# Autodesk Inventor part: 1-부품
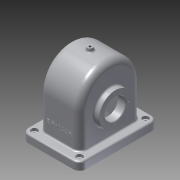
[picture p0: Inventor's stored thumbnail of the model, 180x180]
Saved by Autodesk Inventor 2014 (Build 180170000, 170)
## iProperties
Created: 2016-10
Part Number: 1-부품
Material: 알루미늄-6061
Document SubType Name: Modeling
Designer: SEC
Density: 2.71 g/cm^3
Mass: 1147.19 g
Surface Area: 1199.22 cm^2
Volume: 423.317 cm^3
Appearance: 알루미늄 - 평지
Author: SEC
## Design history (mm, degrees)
sketch "스케치2"
  geometry: L1 (-43, -75)-(43, -75); L2 (55, -63)-(55, 63); L3 (43, 75)-(-43, 75); L4 (-55, 63)-(-55, -63); A1 r 12 centre (-43, 63) between (-43, 75) and (-55, 63); A2 r 12 centre (43, 63) between (55, 63) and (43, 75); A3 r 12 centre (43, -63) between (43, -75) and (55, -63); A4 r 12 centre (-43, -63) between (-55, -63) and (-43, -75); 6 further points
  constraints: 8 end point, 8 point on circle, 8 tangent, 6 point on line, 4 centre point, 3 equal radius, 2 midpoint, 2 parallel, 1 horizontal, 1 horizontal alignment, 1 perpendicular, 1 vertical alignment
  dimensions: "d0" = 110 distance of point (55, 75) point (-55, 75); "d1" = 150 distance of point (55, -75) point (55, 75); "d2" = 12 radius of A1
extrude "돌출1" new body sketch "스케치2" distance "d3" = 15; taper "d4" = 0 deg
sketch "스케치3"
  geometry: A1 r 12 centre (-43, 63) between (-43, 75) and (-55, 63) reference; A2 r 12 centre (-43, -63) between (-55, -63) and (-43, -75) reference; A3 r 12 centre (43, -63) between (43, -75) and (55, -63) reference; A4 r 12 centre (43, 63) between (55, 63) and (43, 75) reference; 5 further points
  constraints: 4 coincident
hole "구멍1" sketch "스케치3" at (-43, -63), (43, -63), (-43, 63), (43, 63) diameter "d7" = 5; stored, may be unused: countersink angle "d11" = 90 deg, drill point angle "d13" = 118 deg; dims "d8" = 6, "d9" = 12, "d10" = 5, "d12" = 8
sketch "스케치5"
  geometry: L1 (58, 80)-(58, 0); L2 (-58, 80)-(-58, 0); L3 (63, 0)-(-63, 0) reference; L4 (-58, 0)-(58, 0); A1 r 58 centre (0, 80) between (58, 80) and (-58, 80); 2 further points
  constraints: 6 end point, 2 point on circle, 2 tangent, 1 centre point, 1 collinear, 1 midpoint, 1 parallel, 1 point on line, 1 vertical, 1 vertical alignment
  dimensions: "d14" = 116 diameter of A1; "d15" = 80 distance from line of L3 A1.centre
extrude "돌출2" join sketch "스케치5" stored distance "d16" = 77; taper "d17" = 0 deg
sketch "스케치6"
  geometry: L1 (-58, 15)-(58, 15) reference; L2 (-58, 80)-(-58, 15) reference; L3 (58, 15)-(58, 80) reference; L4 (-52, 80)-(-52, 0); L5 (52, 0)-(52, 80); L6 (52, 0)-(-52, 0); L7 (63, 0)-(-63, 0) reference; A1 r 58 centre (0, 80) between (58, 80) and (-58, 80) reference; A2 r 52 centre (0, 80) between (52, 80) and (-52, 80); 2 further points
  constraints: 6 end point, 2 midpoint, 2 point on circle, 1 centre point, 1 parallel, 1 perpendicular, 1 tangent, 1 other
  dimensions: "d18" = 6 radial gap between concentric circles of A2 A1
extrude "돌출3" cut sketch "스케치6" stored distance "d19" = 67; taper "d20" = 0 deg
sketch "스케치7"
  geometry: L1 (0, -63)-(0, 63) reference; C1 r 31 at (-65, 0); 2 further points
  constraints: 1 centre point, 1 horizontal alignment, 1 midpoint
  dimensions: "d21" = 62 diameter of C1; "d22" = 65 distance from line of L1 C1.centre
extrude "돌출4" join sketch "스케치7" distance "d23" = 10; taper "d24" = 0 deg
sketch "스케치8"
  geometry: C1 r 31 at (65, 0) reference; C2 r 37.5 at (65, 0); 1 further point
  constraints: 1 centre point, 1 coincident
  dimensions: "d25" = 75 diameter of C2
extrude "돌출5" join sketch "스케치8" distance "d26" = 5; taper "d27" = 0 deg
sketch "스케치9"
  geometry: C1 r 37.5 at (0, 0) reference; C2 r 20 at (0, 0); 1 further point
  constraints: 1 centre point, 1 coincident
  dimensions: "d28" = 40 diameter of C2
extrude "돌출6" cut sketch "스케치9" stored distance "d29" = 5; taper "d30" = 0 deg
sketch "스케치10"
  geometry: L1 (33.5, 102.5)-(19.5, 90.753); L2 (19.5, 90.753)-(19.5, 85); L3 (19.5, 85)-(33.5, 85); L4 (33.5, 85)-(33.5, 102.5); L5 (-33.5, 85)-(-33.5, 45) reference; L6 (-33.5, 65)-(44.153, 65); L7 (33.5, 132)-(33.5, 80) reference; L8 (43.5, 102.5)-(43.5, 27.5) reference; 1 further point
  constraints: 10 end point, 2 parallel, 2 perpendicular, 1 midpoint, 1 point on line, 1 vertical
  dimensions: "d31" = 50 deg angle of L2 L1; "d32" = 40 diameter of L3 L6; "d33" = 75 diameter of L1.start L6; "d34" = 24 distance between parallel lines of L2 L8
revolve "회전1" sketch "스케치10" stored, may be unused: angle "d35" = 90 deg
node "작업 평면1"
sketch "스케치11"
  geometry: C1 r 6 at (0, 0); 1 further point
  constraints: 1 centre point, 1 coincident
  dimensions: "d37" = 12 diameter of C1
extrude "돌출7" join sketch "스케치11" stored distance "d38" = 5; taper "d39" = 0 deg
sketch "스케치12"
  geometry: C1 r 6 at (0, 0) reference; 1 further point
  constraints: 1 coincident
hole "구멍2" sketch "스케치12" at (0, 0) diameter "d40" = 4.459; stored, may be unused: countersink angle "d44" = 90 deg, drill point angle "d46" = 118 deg; dims "d41" = 50, "d42" = 12, "d43" = 5, "d45" = 8
fillet "모깎기1" dims "d47" = 13
fillet "모깎기2" dims "d48" = 8
chamfer "모따기1" distance "d49" = 1; stored, may be unused: second distance "d50" = 2, angle "d51" = 45 deg
fillet "모깎기4" dims "d53" = 3
fillet "모깎기5" dims "d54" = 3
sketch "스케치13"
  geometry: C1 r 37.5 at (0, 0) reference; 2 further points
  constraints: 1 horizontal alignment
  dimensions: "d55" = 29 distance of C1.centre point (29, 0)
hole "구멍3" sketch "스케치13" at (29, 0) diameter "d56" = 2.459; stored, may be unused: countersink angle "d60" = 90 deg, drill point angle "d62" = 118 deg; dims "d57" = 6, "d58" = 12, "d59" = 5, "d61" = 8
sketch "스케치14"
  geometry: C1 r 31 at (0, 0) reference; 2 further points
  constraints: 1 horizontal alignment
  dimensions: "d63" = 26 distance of point (-26, 0) C1.centre
hole "구멍4" sketch "스케치14" at (-26, 0) diameter "d64" = 2.459; stored, may be unused: countersink angle "d68" = 90 deg, drill point angle "d70" = 118 deg; dims "d65" = 6, "d66" = 12, "d67" = 5, "d69" = 8
sketch "스케치15"
  geometry: L1 (-17.5, -80)-(68.5, -80) reference; 3 further points
  constraints: 1 midpoint, 1 vertical alignment, 1 other
  dimensions: "d74" = 40 distance from line of L1 point (25.5, -40)
feature "엠보싱1" sketch "스케치15" dims "d0" = 110, "d1" = 150, "d2" = 12, "d75" = 0.5, "d76" = 0
node "작업 평면2"
feature "면 기울기1" dims angle "d77" = 10 deg
fillet "모깎기6" dims "d78" = 3
fillet "모깎기7" dims "d79" = 3
node "솔리드1"
pattern_circular "원형 패턴1" dims angle "d72" = 360 deg
node "투영된 루프1"
other parameters: "d36" = -144
